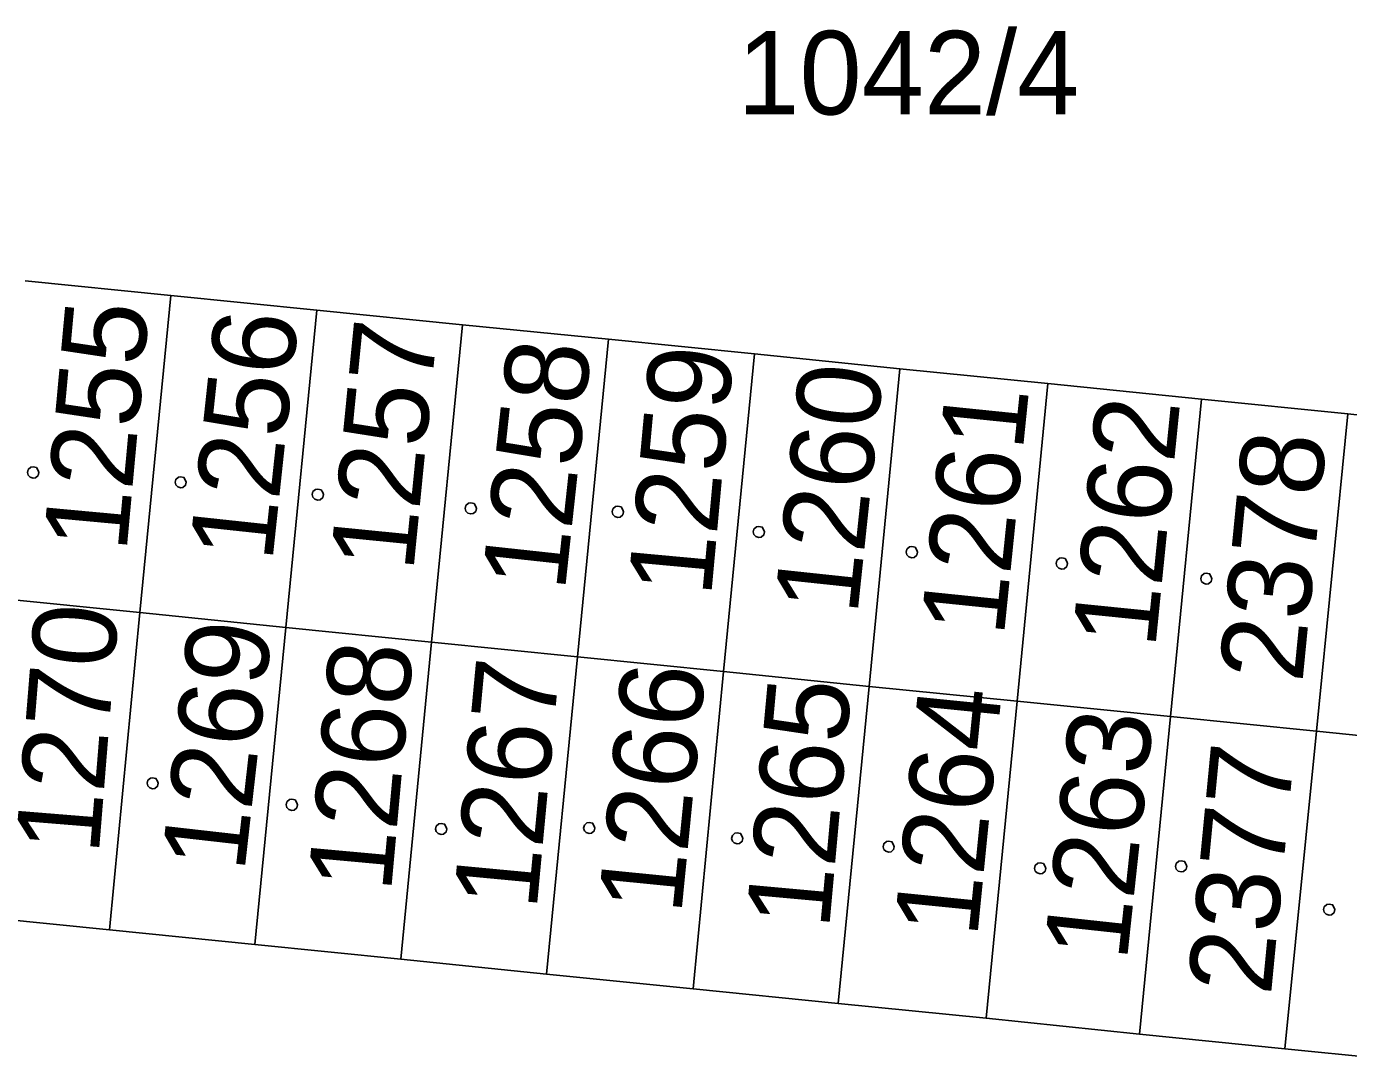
# Model space of a CAD drawing. Extents: x -777309 to -774195, y -1144706 to -1143600.
# Drawn here: x -775160.51 to -775133.62, y -1144418.54 to -1144397.43 of the extents above; entities that cross this region are included whole.
import ezdxf

# ---------------------------------------------------------------- set-up
doc = ezdxf.new("R2010")
doc.units = 0
for name, color, linetype in [('1', 7, 'Continuous'), ('12', 7, 'Continuous'), ('2', 7, 'Continuous'), ('5', 7, 'Continuous')]:
    doc.layers.add(name, color=color, linetype=linetype)

msp = doc.modelspace()

# ---------------------------------------------------------------- linework, layer by layer
at = {"layer": '1'}
for p, q in [((-775157.57, -1144402.9), (-775160.53, -1144402.6)), ((-775158.2, -1144409.35), (-775157.57, -1144402.9)), ((-775154.6, -1144403.2), (-775157.57, -1144402.9)), ((-775154.6, -1144403.2), (-775155.23, -1144409.65)), ((-775151.64, -1144403.5), (-775154.6, -1144403.2)), ((-775152.27, -1144409.95), (-775151.64, -1144403.5)), ((-775148.67, -1144403.79), (-775151.64, -1144403.5)), ((-775148.67, -1144403.79), (-775149.3, -1144410.25)), ((-775145.7, -1144404.09), (-775148.67, -1144403.79)), ((-775146.33, -1144410.55), (-775145.7, -1144404.09)), ((-775142.74, -1144404.39), (-775145.7, -1144404.09)), ((-775142.74, -1144404.39), (-775143.37, -1144410.85)), ((-775139.73, -1144404.69), (-775142.74, -1144404.39)), ((-775140.36, -1144411.15), (-775139.73, -1144404.69)), ((-775136.61, -1144405.01), (-775139.73, -1144404.69)), ((-775136.61, -1144405.01), (-775137.24, -1144411.46)), ((-775133.63, -1144405.31), (-775136.61, -1144405.01)), ((-775134.27, -1144411.76), (-775133.63, -1144405.31)), ((-775130.42, -1144405.63), (-775133.63, -1144405.31)), ((-775158.2, -1144409.35), (-775161.16, -1144409.05)), ((-775158.82, -1144415.8), (-775158.2, -1144409.35)), ((-775155.23, -1144409.65), (-775158.2, -1144409.35)), ((-775155.23, -1144409.65), (-775155.86, -1144416.1)), ((-775152.27, -1144409.95), (-775155.23, -1144409.65)), ((-775152.89, -1144416.4), (-775152.27, -1144409.95)), ((-775149.3, -1144410.25), (-775152.27, -1144409.95)), ((-775149.3, -1144410.25), (-775149.93, -1144416.7)), ((-775146.33, -1144410.55), (-775149.3, -1144410.25)), ((-775146.95, -1144417), (-775146.33, -1144410.55)), ((-775143.37, -1144410.85), (-775146.33, -1144410.55)), ((-775143.37, -1144410.85), (-775144, -1144417.3)), ((-775140.36, -1144411.15), (-775143.37, -1144410.85)), ((-775140.99, -1144417.6), (-775140.36, -1144411.15)), ((-775137.24, -1144411.46), (-775140.36, -1144411.15)), ((-775137.24, -1144411.46), (-775137.87, -1144417.92)), ((-775134.27, -1144411.76), (-775137.24, -1144411.46)), ((-775134.91, -1144418.22), (-775134.27, -1144411.76)), ((-775131.06, -1144412.09), (-775134.27, -1144411.76)), ((-775161.79, -1144415.5), (-775158.82, -1144415.8)), ((-775158.82, -1144415.8), (-775155.86, -1144416.1)), ((-775155.86, -1144416.1), (-775152.89, -1144416.4)), ((-775152.89, -1144416.4), (-775149.93, -1144416.7)), ((-775149.93, -1144416.7), (-775146.95, -1144417)), ((-775146.95, -1144417), (-775144, -1144417.3)), ((-775144, -1144417.3), (-775140.99, -1144417.6)), ((-775140.99, -1144417.6), (-775137.87, -1144417.92)), ((-775137.87, -1144417.92), (-775134.91, -1144418.22)), ((-775134.91, -1144418.22), (-775131.7, -1144418.54))]:
    msp.add_line(p, q, dxfattribs=at)
at = {"layer": '12'}
for p, q in [((-775157.57, -1144402.9), (-775160.53, -1144402.6)), ((-775158.2, -1144409.35), (-775157.57, -1144402.9)), ((-775158.2, -1144409.35), (-775157.57, -1144402.9)), ((-775154.6, -1144403.2), (-775157.57, -1144402.9)), ((-775154.6, -1144403.2), (-775155.23, -1144409.65)), ((-775154.6, -1144403.2), (-775155.23, -1144409.65)), ((-775151.64, -1144403.5), (-775154.6, -1144403.2)), ((-775152.27, -1144409.95), (-775151.64, -1144403.5)), ((-775152.27, -1144409.95), (-775151.64, -1144403.5)), ((-775148.67, -1144403.79), (-775151.64, -1144403.5)), ((-775148.67, -1144403.79), (-775149.3, -1144410.25)), ((-775148.67, -1144403.79), (-775149.3, -1144410.25)), ((-775145.7, -1144404.09), (-775148.67, -1144403.79)), ((-775146.33, -1144410.55), (-775145.7, -1144404.09)), ((-775146.33, -1144410.55), (-775145.7, -1144404.09)), ((-775142.74, -1144404.39), (-775145.7, -1144404.09)), ((-775142.74, -1144404.39), (-775143.37, -1144410.85)), ((-775142.74, -1144404.39), (-775143.37, -1144410.85)), ((-775139.73, -1144404.69), (-775142.74, -1144404.39)), ((-775140.36, -1144411.15), (-775139.73, -1144404.69)), ((-775140.36, -1144411.15), (-775139.73, -1144404.69)), ((-775136.61, -1144405.01), (-775139.73, -1144404.69)), ((-775136.61, -1144405.01), (-775137.24, -1144411.46)), ((-775136.61, -1144405.01), (-775137.24, -1144411.46)), ((-775133.63, -1144405.31), (-775136.61, -1144405.01)), ((-775134.27, -1144411.76), (-775133.63, -1144405.31)), ((-775134.27, -1144411.76), (-775133.63, -1144405.31)), ((-775130.42, -1144405.63), (-775133.63, -1144405.31)), ((-775158.2, -1144409.35), (-775161.16, -1144409.05)), ((-775158.2, -1144409.35), (-775161.16, -1144409.05)), ((-775158.82, -1144415.8), (-775158.2, -1144409.35)), ((-775158.82, -1144415.8), (-775158.2, -1144409.35)), ((-775155.23, -1144409.65), (-775158.2, -1144409.35)), ((-775155.23, -1144409.65), (-775158.2, -1144409.35)), ((-775155.23, -1144409.65), (-775155.86, -1144416.1)), ((-775155.23, -1144409.65), (-775155.86, -1144416.1)), ((-775152.27, -1144409.95), (-775155.23, -1144409.65)), ((-775152.27, -1144409.95), (-775155.23, -1144409.65)), ((-775152.89, -1144416.4), (-775152.27, -1144409.95)), ((-775152.89, -1144416.4), (-775152.27, -1144409.95)), ((-775149.3, -1144410.25), (-775152.27, -1144409.95)), ((-775149.3, -1144410.25), (-775152.27, -1144409.95)), ((-775149.3, -1144410.25), (-775149.93, -1144416.7)), ((-775149.3, -1144410.25), (-775149.93, -1144416.7)), ((-775146.33, -1144410.55), (-775149.3, -1144410.25)), ((-775146.33, -1144410.55), (-775149.3, -1144410.25)), ((-775146.95, -1144417), (-775146.33, -1144410.55)), ((-775146.95, -1144417), (-775146.33, -1144410.55)), ((-775143.37, -1144410.85), (-775146.33, -1144410.55)), ((-775143.37, -1144410.85), (-775146.33, -1144410.55)), ((-775143.37, -1144410.85), (-775144, -1144417.3)), ((-775143.37, -1144410.85), (-775144, -1144417.3)), ((-775140.36, -1144411.15), (-775143.37, -1144410.85)), ((-775140.36, -1144411.15), (-775143.37, -1144410.85)), ((-775140.99, -1144417.6), (-775140.36, -1144411.15)), ((-775140.99, -1144417.6), (-775140.36, -1144411.15)), ((-775137.24, -1144411.46), (-775140.36, -1144411.15)), ((-775137.24, -1144411.46), (-775140.36, -1144411.15)), ((-775137.24, -1144411.46), (-775137.87, -1144417.92)), ((-775137.24, -1144411.46), (-775137.87, -1144417.92)), ((-775134.27, -1144411.76), (-775137.24, -1144411.46)), ((-775134.27, -1144411.76), (-775137.24, -1144411.46)), ((-775134.91, -1144418.22), (-775134.27, -1144411.76)), ((-775134.91, -1144418.22), (-775134.27, -1144411.76)), ((-775131.06, -1144412.09), (-775134.27, -1144411.76)), ((-775131.06, -1144412.09), (-775134.27, -1144411.76)), ((-775161.79, -1144415.5), (-775158.82, -1144415.8)), ((-775158.82, -1144415.8), (-775155.86, -1144416.1)), ((-775155.86, -1144416.1), (-775152.89, -1144416.4)), ((-775152.89, -1144416.4), (-775149.93, -1144416.7)), ((-775149.93, -1144416.7), (-775146.95, -1144417)), ((-775146.95, -1144417), (-775144, -1144417.3)), ((-775144, -1144417.3), (-775140.99, -1144417.6)), ((-775140.99, -1144417.6), (-775137.87, -1144417.92)), ((-775137.87, -1144417.92), (-775134.91, -1144418.22)), ((-775134.91, -1144418.22), (-775131.7, -1144418.54))]:
    msp.add_line(p, q, dxfattribs=at)
at = {"layer": '5'}
for points in [[(-775160.37, -1144406.386), (-775160.303, -1144406.4), (-775160.269, -1144406.46), (-775160.256, -1144406.5), (-775160.269, -1144406.56), (-775160.323, -1144406.607), (-775160.37, -1144406.614), (-775160.43, -1144406.594), (-775160.471, -1144406.554), (-775160.484, -1144406.5), (-775160.471, -1144406.44), (-775160.417, -1144406.393)], [(-775157.37, -1144406.586), (-775157.303, -1144406.6), (-775157.269, -1144406.66), (-775157.256, -1144406.7), (-775157.269, -1144406.76), (-775157.323, -1144406.807), (-775157.37, -1144406.814), (-775157.43, -1144406.794), (-775157.471, -1144406.754), (-775157.484, -1144406.7), (-775157.471, -1144406.64), (-775157.417, -1144406.593)], [(-775154.58, -1144406.836), (-775154.513, -1144406.85), (-775154.479, -1144406.91), (-775154.466, -1144406.95), (-775154.479, -1144407.01), (-775154.533, -1144407.057), (-775154.58, -1144407.064), (-775154.64, -1144407.044), (-775154.681, -1144407.004), (-775154.694, -1144406.95), (-775154.681, -1144406.89), (-775154.627, -1144406.843)], [(-775151.47, -1144407.116), (-775151.403, -1144407.13), (-775151.369, -1144407.19), (-775151.356, -1144407.23), (-775151.369, -1144407.29), (-775151.423, -1144407.337), (-775151.47, -1144407.344), (-775151.53, -1144407.324), (-775151.57, -1144407.284), (-775151.584, -1144407.23), (-775151.57, -1144407.17), (-775151.517, -1144407.123)], [(-775148.48, -1144407.186), (-775148.413, -1144407.2), (-775148.38, -1144407.26), (-775148.366, -1144407.3), (-775148.38, -1144407.36), (-775148.433, -1144407.407), (-775148.48, -1144407.414), (-775148.54, -1144407.394), (-775148.581, -1144407.354), (-775148.594, -1144407.3), (-775148.581, -1144407.24), (-775148.527, -1144407.193)], [(-775145.61, -1144407.596), (-775145.543, -1144407.61), (-775145.509, -1144407.67), (-775145.496, -1144407.71), (-775145.509, -1144407.77), (-775145.563, -1144407.817), (-775145.61, -1144407.824), (-775145.67, -1144407.804), (-775145.711, -1144407.764), (-775145.724, -1144407.71), (-775145.711, -1144407.65), (-775145.657, -1144407.603)], [(-775142.5, -1144408.006), (-775142.433, -1144408.02), (-775142.4, -1144408.08), (-775142.386, -1144408.12), (-775142.4, -1144408.18), (-775142.453, -1144408.227), (-775142.5, -1144408.234), (-775142.56, -1144408.214), (-775142.601, -1144408.174), (-775142.614, -1144408.12), (-775142.601, -1144408.06), (-775142.547, -1144408.013)], [(-775139.45, -1144408.236), (-775139.383, -1144408.25), (-775139.35, -1144408.31), (-775139.336, -1144408.35), (-775139.35, -1144408.41), (-775139.403, -1144408.457), (-775139.45, -1144408.464), (-775139.51, -1144408.444), (-775139.55, -1144408.404), (-775139.564, -1144408.35), (-775139.55, -1144408.29), (-775139.497, -1144408.243)], [(-775136.51, -1144408.546), (-775136.443, -1144408.559), (-775136.41, -1144408.62), (-775136.396, -1144408.66), (-775136.41, -1144408.72), (-775136.463, -1144408.767), (-775136.51, -1144408.774), (-775136.57, -1144408.754), (-775136.611, -1144408.714), (-775136.624, -1144408.66), (-775136.611, -1144408.6), (-775136.557, -1144408.553)], [(-775157.94, -1144412.706), (-775157.873, -1144412.72), (-775157.84, -1144412.78), (-775157.826, -1144412.82), (-775157.84, -1144412.88), (-775157.893, -1144412.927), (-775157.94, -1144412.934), (-775158, -1144412.914), (-775158.04, -1144412.874), (-775158.054, -1144412.82), (-775158.04, -1144412.76), (-775157.987, -1144412.713)], [(-775155.11, -1144413.146), (-775155.043, -1144413.16), (-775155.009, -1144413.22), (-775154.996, -1144413.26), (-775155.009, -1144413.32), (-775155.063, -1144413.367), (-775155.11, -1144413.374), (-775155.17, -1144413.354), (-775155.211, -1144413.314), (-775155.224, -1144413.26), (-775155.211, -1144413.2), (-775155.157, -1144413.153)], [(-775152.07, -1144413.636), (-775152.003, -1144413.65), (-775151.969, -1144413.71), (-775151.956, -1144413.75), (-775151.969, -1144413.81), (-775152.023, -1144413.857), (-775152.07, -1144413.864), (-775152.13, -1144413.844), (-775152.171, -1144413.804), (-775152.184, -1144413.75), (-775152.171, -1144413.69), (-775152.117, -1144413.643)], [(-775149.06, -1144413.616), (-775148.993, -1144413.63), (-775148.96, -1144413.69), (-775148.946, -1144413.73), (-775148.96, -1144413.79), (-775149.013, -1144413.837), (-775149.06, -1144413.844), (-775149.12, -1144413.824), (-775149.16, -1144413.784), (-775149.174, -1144413.73), (-775149.16, -1144413.67), (-775149.107, -1144413.623)], [(-775146.05, -1144413.826), (-775145.983, -1144413.84), (-775145.949, -1144413.9), (-775145.936, -1144413.94), (-775145.949, -1144414), (-775146.003, -1144414.047), (-775146.05, -1144414.054), (-775146.11, -1144414.034), (-775146.15, -1144413.994), (-775146.164, -1144413.94), (-775146.15, -1144413.88), (-775146.097, -1144413.833)], [(-775142.97, -1144413.996), (-775142.903, -1144414.01), (-775142.869, -1144414.07), (-775142.856, -1144414.11), (-775142.869, -1144414.17), (-775142.923, -1144414.217), (-775142.97, -1144414.224), (-775143.03, -1144414.204), (-775143.07, -1144414.164), (-775143.084, -1144414.11), (-775143.07, -1144414.05), (-775143.017, -1144414.003)], [(-775139.89, -1144414.436), (-775139.823, -1144414.45), (-775139.79, -1144414.51), (-775139.776, -1144414.55), (-775139.79, -1144414.61), (-775139.843, -1144414.657), (-775139.89, -1144414.664), (-775139.95, -1144414.644), (-775139.991, -1144414.604), (-775140.004, -1144414.55), (-775139.991, -1144414.49), (-775139.937, -1144414.443)], [(-775137.02, -1144414.396), (-775136.953, -1144414.41), (-775136.92, -1144414.47), (-775136.906, -1144414.51), (-775136.92, -1144414.57), (-775136.973, -1144414.617), (-775137.02, -1144414.624), (-775137.08, -1144414.604), (-775137.12, -1144414.564), (-775137.134, -1144414.51), (-775137.12, -1144414.45), (-775137.067, -1144414.403)], [(-775134.01, -1144415.276), (-775133.943, -1144415.289), (-775133.91, -1144415.35), (-775133.896, -1144415.39), (-775133.91, -1144415.45), (-775133.963, -1144415.497), (-775134.01, -1144415.504), (-775134.07, -1144415.484), (-775134.111, -1144415.444), (-775134.124, -1144415.39), (-775134.111, -1144415.33), (-775134.057, -1144415.283)]]:
    msp.add_lwpolyline(points, close=True, dxfattribs=at)

# ---------------------------------------------------------------- texts
at = {"layer": '2'}
msp.add_text('1042/4', height=1.7, dxfattribs=at).set_placement((-775146.047, -1144399.22))
for s, rotation, p in [('1255', 84.7405, (-775158.474, -1144408.139)), ('1256', 83.881, (-775155.508, -1144408.34)), ('1257', 84.3394, (-775152.641, -1144408.539)), ('1258', 83.8237, (-775149.558, -1144408.94)), ('1259', 84.7405, (-775146.584, -1144409.049)), ('1260', 83.9383, (-775143.609, -1144409.419)), ('1261', 84.1675, (-775140.63, -1144409.859)), ('1262', 84.2248, (-775137.55, -1144410.099)), ('2378', 84.3967, (-775134.557, -1144410.794)), ('1270', 85.3707, (-775159.038, -1144414.289)), ('1269', 83.5372, (-775156.076, -1144414.65)), ('1268', 84.7978, (-775153.094, -1144415.059)), ('1267', 84.6259, (-775150.133, -1144415.419)), ('1266', 84.3394, (-775147.191, -1144415.509)), ('1265', 84.7978, (-775144.184, -1144415.809)), ('1264', 84.2821, (-775141.171, -1144415.979)), ('1263', 83.8237, (-775138.128, -1144416.46)), ('2377', 84.5113, (-775135.197, -1144417.154))]:
    msp.add_text(s, height=1.7, rotation=rotation, dxfattribs=at).set_placement(p)

doc.saveas('drawing.dxf')
